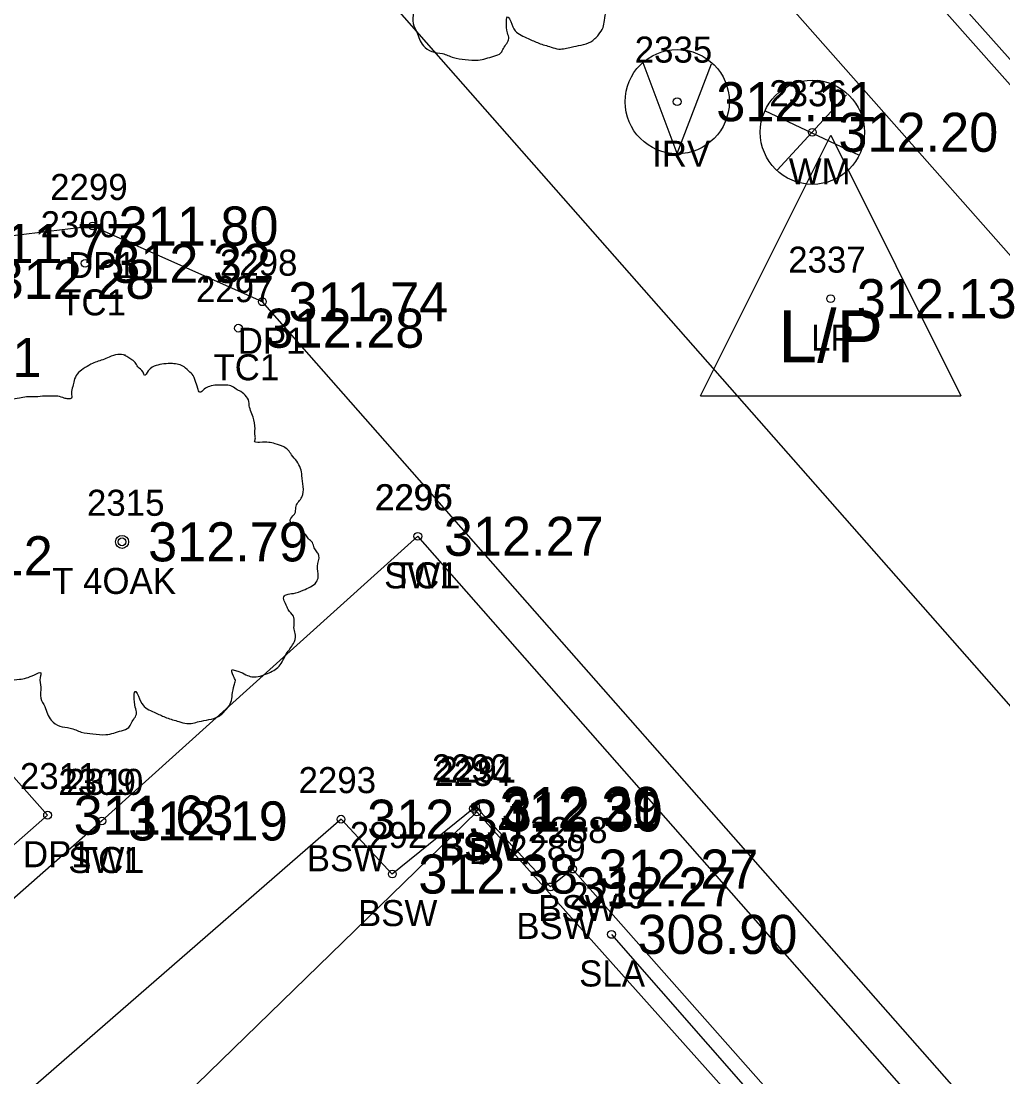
# Model space of a CAD drawing. Extents: x 1970076 to 1971136, y 803126 to 804215.
# Drawn here: x 1970346.97 to 1970384.66, y 803730.64 to 803771.17 of the extents above; entities that cross this region are included whole.
import ezdxf

# ---------------------------------------------------------------- set-up
doc = ezdxf.new("R2010")
doc.units = 0
for name, color, linetype in [('RD_EX_Bldg', 7, 'Continuous'), ('RD_EX_Bldg_txCode', 7, 'Continuous'), ('RD_EX_BldgApp', 7, 'Continuous'), ('RD_EX_Conc', 7, 'Continuous'), ('RD_EX_Conc_txCode', 7, 'Continuous'), ('RD_EX_Driveway', 7, 'Continuous'), ('RD_EX_Driveway_txCode', 7, 'Continuous'), ('RD_EX_Misc_txCode', 7, 'Continuous'), ('RD_EX_TX_Bldg_ELEV', 7, 'Continuous'), ('RD_EX_TX_Conc_ELEV', 7, 'Continuous'), ('RD_EX_TX_Driveway_ELEV', 7, 'Continuous'), ('RD_EX_TX_Misc_ELEV', 7, 'Continuous'), ('RD_EX_TX_UT_ELEV', 7, 'Continuous'), ('RD_EX_TX_VEG_ELEV', 7, 'Continuous'), ('RD_EX_UT', 7, 'Continuous'), ('RD_EX_UT_txCode', 7, 'Continuous'), ('RD_EX_VEG', 7, 'Continuous'), ('RD_EX_VEG_txCode', 7, 'Continuous'), ('RD_SMD_Locator', 7, 'Continuous')]:
    doc.layers.add(name, color=color, linetype=linetype)

msp = doc.modelspace()

# ---------------------------------------------------------------- linework, layer by layer
at = {"layer": 'RD_EX_Bldg'}
msp.add_lwpolyline([(1970316.239, 803648.649), (1970363.887, 803689.383), (1970360.372, 803693.374), (1970387.334, 803715.199), (1970364.462, 803740.807), (1970337.816, 803714.899), (1970333.809, 803719.759), (1970289.788, 803679.246), (1970316.239, 803648.649)], dxfattribs=at)
at = {"layer": 'RD_EX_BldgApp'}
for q in [(1970370.85, 803769.569), (1970373.476, 803769.532)]:
    msp.add_line((1970372.154, 803766.087), q, dxfattribs=at)
for radius in [2, 0.15]:
    msp.add_circle((1970372.154, 803768.079), radius, dxfattribs=at)
at = {"layer": 'RD_EX_Conc'}
msp.add_line((1970389.201, 803764.895), (1970371.192, 803785.158), dxfattribs=at)
for points in [[(1970403.64, 803748.467), (1970397.536, 803754.406), (1970390.789, 803761.917), (1970388.776, 803764.406), (1970370.879, 803784.584), (1970367.637, 803785.738), (1970364.866, 803784.899)], [(1970403.64, 803748.467), (1970400.496, 803744.573), (1970364.866, 803784.899)], [(1970388.043, 803714.574), (1970387.812, 803720.9), (1970384.41, 803726.133), (1970362.198, 803751.392), (1970350.072, 803740.463), (1970336.455, 803728.473)], [(1970388.043, 803714.574), (1970384.866, 803718.144), (1970385.631, 803718.829), (1970368.137, 803738.615), (1970367.294, 803737.93), (1970364.409, 803741.02), (1970364.338, 803740.936), (1970361.218, 803738.424), (1970359.252, 803740.53), (1970341.72, 803725.277)]]:
    msp.add_lwpolyline(points, dxfattribs=at)
at = {"layer": 'RD_EX_Driveway'}
for points in [[(1970401.094, 803743.669), (1970397.555, 803740.019), (1970391.952, 803738.507), (1970389.106, 803740.151), (1970358.957, 803774.425), (1970357.83, 803778.256), (1970359.349, 803782.137), (1970363.728, 803785.997), (1970367.42, 803786.267), (1970367.42, 803786.267), (1970371.192, 803785.158)], [(1970361.584, 803685.25), (1970385.155, 803706.07), (1970389.475, 803713.845), (1970389.303, 803721.405), (1970385.523, 803727.117), (1970356.232, 803760.398), (1970349.717, 803763.304), (1970344.215, 803762.632), (1970339.473, 803759.052), (1970338.114, 803753.777), (1970339.901, 803749.792), (1970347.988, 803740.685), (1970335.512, 803729.688)]]:
    msp.add_lwpolyline(points, dxfattribs=at)
at = {"layer": 'RD_EX_UT'}
for p, q in [((1970375.989, 803765.446), (1970378.657, 803768.342)), ((1970375.508, 803767.741), (1970379.139, 803766.028)), ((1970373.046, 803756.791), (1970378.046, 803766.791)), ((1970378.046, 803766.791), (1970383.046, 803756.791)), ((1970373.046, 803756.791), (1970383.046, 803756.791))]:
    msp.add_line(p, q, dxfattribs=at)
msp.add_circle((1970377.342, 803766.904), 2, dxfattribs=at)
at = {"layer": 'RD_EX_VEG'}
msp.add_line((1970369.634, 803736.106), (1970383.155, 803720.666), dxfattribs=at)
for centre, radius in [((1970350.846, 803751.179), 0.25), ((1970350.834, 803751.16), 0.0001)]:
    msp.add_circle(centre, radius, dxfattribs=at)
for points in [[(1970365.264, 803784.246), (1970364.964, 803784.271), (1970364.639, 803784.171), (1970364.39, 803784.071), (1970364.165, 803783.996), (1970363.94, 803783.896), (1970363.64, 803783.721), (1970363.415, 803783.521), (1970363.29, 803783.272), (1970363.24, 803783.047), (1970363.19, 803782.772), (1970363.19, 803782.597), (1970363.065, 803782.572), (1970362.915, 803782.597), (1970362.665, 803782.672), (1970362.415, 803782.672), (1970362.165, 803782.672), (1970361.816, 803782.647), (1970361.466, 803782.647), (1970361.191, 803782.597), (1970360.866, 803782.547), (1970360.491, 803782.422), (1970360.141, 803782.297), (1970359.842, 803782.047), (1970359.592, 803781.572), (1970359.467, 803781.222), (1970359.317, 803780.973), (1970359.467, 803780.523), (1970359.642, 803780.173), (1970359.667, 803779.973), (1970359.742, 803779.548), (1970359.842, 803779.323), (1970359.966, 803779.123), (1970359.892, 803779.098), (1970359.517, 803779.048), (1970359.217, 803778.948), (1970358.792, 803778.724), (1970358.567, 803778.499), (1970358.467, 803778.174), (1970358.442, 803777.824), (1970358.342, 803777.624), (1970358.267, 803777.349), (1970358.242, 803777.274), (1970358.192, 803776.949), (1970358.292, 803776.499), (1970358.317, 803776.15), (1970358.442, 803775.925), (1970358.592, 803775.75), (1970358.767, 803775.5), (1970359.167, 803775.275), (1970359.492, 803775.175), (1970359.692, 803775.15), (1970359.517, 803774.65), (1970359.467, 803774.3), (1970359.342, 803773.901), (1970359.342, 803773.826), (1970359.292, 803773.351), (1970359.442, 803773.026), (1970359.517, 803772.651), (1970359.692, 803772.426), (1970359.966, 803772.126), (1970360.291, 803771.902), (1970360.791, 803771.777), (1970361.191, 803771.802), (1970361.766, 803771.976), (1970362.016, 803772.051), (1970361.991, 803771.877), (1970362.016, 803771.502), (1970362.016, 803771.077), (1970362.165, 803770.752), (1970362.265, 803770.477), (1970362.415, 803770.227), (1970362.74, 803770.002), (1970363.14, 803769.927), (1970363.565, 803769.777), (1970364.015, 803769.702), (1970364.514, 803769.677), (1970365.114, 803769.827), (1970365.389, 803769.952), (1970365.489, 803770.127), (1970365.689, 803770.502), (1970365.639, 803770.727), (1970365.664, 803771.327), (1970365.764, 803771.152), (1970365.939, 803770.802), (1970366.439, 803770.502), (1970366.838, 803770.327), (1970367.313, 803770.177), (1970367.613, 803770.102), (1970368.088, 803770.177), (1970368.463, 803770.252), (1970368.838, 803770.377), (1970369.137, 803770.652), (1970369.312, 803770.927), (1970369.362, 803771.202), (1970369.437, 803771.577), (1970369.487, 803771.752)], [(1970350.978, 803758.346), (1970350.678, 803758.371), (1970350.353, 803758.271), (1970350.103, 803758.171), (1970349.879, 803758.096), (1970349.654, 803757.996), (1970349.354, 803757.821), (1970349.129, 803757.621), (1970349.004, 803757.371), (1970348.954, 803757.146), (1970348.904, 803756.872), (1970348.904, 803756.697), (1970348.779, 803756.672), (1970348.629, 803756.697), (1970348.379, 803756.772), (1970348.129, 803756.772), (1970347.879, 803756.772), (1970347.53, 803756.747), (1970347.18, 803756.747), (1970346.905, 803756.697), (1970346.58, 803756.647), (1970346.205, 803756.522), (1970345.855, 803756.397), (1970345.555, 803756.147), (1970345.306, 803755.672), (1970345.181, 803755.322), (1970345.031, 803755.072), (1970345.181, 803754.623), (1970345.356, 803754.273), (1970345.38, 803754.073), (1970345.455, 803753.648), (1970345.555, 803753.423), (1970345.68, 803753.223), (1970345.605, 803753.198), (1970345.231, 803753.148), (1970344.931, 803753.048), (1970344.506, 803752.823), (1970344.281, 803752.598), (1970344.181, 803752.274), (1970344.156, 803751.924), (1970344.056, 803751.724), (1970343.981, 803751.449), (1970343.956, 803751.374), (1970343.906, 803751.049), (1970344.006, 803750.599), (1970344.031, 803750.249), (1970344.156, 803750.025), (1970344.306, 803749.85), (1970344.481, 803749.6), (1970344.881, 803749.375), (1970345.206, 803749.275), (1970345.405, 803749.25), (1970345.231, 803748.75), (1970345.181, 803748.4), (1970345.056, 803748), (1970345.056, 803747.926), (1970345.006, 803747.451), (1970345.156, 803747.126), (1970345.231, 803746.751), (1970345.405, 803746.526), (1970345.68, 803746.226), (1970346.005, 803746.001), (1970346.505, 803745.876), (1970346.905, 803745.901), (1970347.48, 803746.076), (1970347.729, 803746.151), (1970347.704, 803745.976), (1970347.729, 803745.601), (1970347.729, 803745.177), (1970347.879, 803744.852), (1970347.979, 803744.577), (1970348.129, 803744.327), (1970348.454, 803744.102), (1970348.854, 803744.027), (1970349.279, 803743.877), (1970349.729, 803743.802), (1970350.228, 803743.777), (1970350.828, 803743.927), (1970351.103, 803744.052), (1970351.203, 803744.227), (1970351.403, 803744.602), (1970351.353, 803744.827), (1970351.378, 803745.427), (1970351.478, 803745.252), (1970351.653, 803744.902), (1970352.153, 803744.602), (1970352.552, 803744.427), (1970353.027, 803744.277), (1970353.327, 803744.202), (1970353.802, 803744.277), (1970354.177, 803744.352), (1970354.551, 803744.477), (1970354.851, 803744.752), (1970355.026, 803745.027), (1970355.076, 803745.302), (1970355.151, 803745.676), (1970355.201, 803745.851)], [(1970355.201, 803745.851), (1970355.126, 803746.026), (1970355.076, 803746.276), (1970355.151, 803746.251), (1970355.326, 803746.201), (1970355.601, 803746.076), (1970355.826, 803746.001), (1970356.151, 803746.026), (1970356.426, 803746.126), (1970356.875, 803746.401), (1970357.15, 803746.876), (1970357.425, 803747.276), (1970357.5, 803747.601), (1970357.45, 803747.826), (1970357.425, 803748.325), (1970357.225, 803748.575), (1970357.175, 803748.7), (1970357.075, 803749.1), (1970357.15, 803749.15), (1970357.425, 803749.2), (1970357.8, 803749.325), (1970358.075, 803749.45), (1970358.3, 803749.625), (1970358.375, 803749.85), (1970358.35, 803750.249), (1970358.4, 803750.649), (1970358.325, 803750.799), (1970358.225, 803750.949), (1970358.15, 803751.149), (1970358, 803751.299), (1970357.9, 803751.449), (1970357.8, 803751.549), (1970357.675, 803751.699), (1970357.5, 803751.824), (1970357.35, 803751.874), (1970357.3, 803752.024), (1970357.45, 803752.224), (1970357.5, 803752.324), (1970357.525, 803752.548), (1970357.75, 803752.898), (1970357.8, 803753.298), (1970357.75, 803753.723), (1970357.7, 803753.998), (1970357.55, 803754.273), (1970357.35, 803754.523), (1970357.225, 803754.698), (1970357.05, 803754.822), (1970356.726, 803754.947), (1970356.476, 803754.997), (1970356.126, 803754.997), (1970355.926, 803755.047), (1970355.951, 803755.097), (1970355.951, 803755.247), (1970355.951, 803755.522), (1970355.876, 803755.972), (1970355.726, 803756.472), (1970355.726, 803756.497), (1970355.626, 803756.747), (1970355.401, 803756.947), (1970355.226, 803757.046), (1970355.026, 803757.171), (1970354.776, 803757.196), (1970354.477, 803757.196), (1970354.202, 803757.146), (1970354.002, 803757.046), (1970353.827, 803756.922), (1970353.752, 803757.071), (1970353.652, 803757.371), (1970353.602, 803757.521), (1970353.452, 803757.696), (1970353.227, 803757.896), (1970352.777, 803758.021), (1970352.153, 803757.946), (1970351.853, 803757.746), (1970351.703, 803757.571), (1970351.653, 803757.696), (1970351.453, 803757.896), (1970351.353, 803758.071), (1970351.178, 803758.196), (1970351.028, 803758.296), (1970350.928, 803758.346)]]:
    msp.add_spline(points, degree=3, dxfattribs=at)
at = {"layer": 'RD_SMD_Locator'}
for centre in [(1970377.342, 803766.904), (1970349.717, 803763.304), (1970349.43, 803761.874), (1970356.232, 803760.398), (1970378.046, 803760.515), (1970355.314, 803759.382), (1970362.198, 803751.392), (1970362.198, 803751.392), (1970350.846, 803751.179), (1970364.338, 803740.936), (1970364.409, 803741.02), (1970364.462, 803740.807), (1970347.988, 803740.685), (1970350.072, 803740.463), (1970350.072, 803740.463), (1970359.252, 803740.53), (1970361.218, 803738.424), (1970368.137, 803738.615), (1970367.294, 803737.93), (1970369.634, 803736.106)]:
    msp.add_circle(centre, 0.15, dxfattribs=at)

# ---------------------------------------------------------------- texts
at = {"layer": 'RD_EX_Bldg_txCode'}
for s, p in [('2234', (1970362.832, 803741.807)), ('B', (1970364.155, 803738.807))]:
    msp.add_text(s, height=1, dxfattribs=at).set_placement(p)
at = {"layer": 'RD_EX_Conc_txCode'}
for s, p in [('2300', (1970347.721, 803762.874)), ('2297', (1970353.684, 803760.382)), ('TC1', (1970348.469, 803759.874)), ('TC1', (1970354.353, 803757.382)), ('2296', (1970360.544, 803752.392)), ('2295', (1970360.568, 803752.392)), ('SWL', (1970360.907, 803749.392)), ('TC1', (1970361.237, 803749.392)), ('2290', (1970362.74, 803742.02)), ('2291', (1970362.992, 803741.936)), ('2309', (1970348.403, 803741.463)), ('2310', (1970348.686, 803741.463)), ('2293', (1970357.622, 803741.53)), ('2288', (1970366.507, 803739.615)), ('2292', (1970359.588, 803739.424)), ('BSW', (1970363.023, 803738.936)), ('BSW', (1970363.094, 803739.02)), ('2289', (1970365.664, 803738.93)), ('SWL', (1970348.781, 803738.463)), ('TC1', (1970349.111, 803738.463)), ('BSW', (1970357.937, 803738.53)), ('BSW', (1970359.903, 803736.424)), ('BSW', (1970366.822, 803736.615)), ('BSW', (1970365.979, 803735.93))]:
    msp.add_text(s, height=1, dxfattribs=at).set_placement(p)
at = {"layer": 'RD_EX_Driveway_txCode'}
for s, p in [('2299', (1970348.087, 803764.304)), ('DP1', (1970348.772, 803761.304)), ('2298', (1970354.602, 803761.398)), ('DP1', (1970355.287, 803758.398)), ('2311', (1970346.925, 803741.685)), ('DP1', (1970347.043, 803738.685))]:
    msp.add_text(s, height=1, dxfattribs=at).set_placement(p)
at = {"layer": 'RD_EX_Misc_txCode'}
for s, p in [('2335', (1970370.524, 803769.579)), ('IRV', (1970371.193, 803765.579))]:
    msp.add_text(s, height=1, dxfattribs=at).set_placement(p)
at = {"layer": 'RD_EX_TX_Bldg_ELEV'}
msp.add_text('312.30', height=1.5, dxfattribs=at).set_placement((1970365.462, 803740.057))
at = {"layer": 'RD_EX_TX_Conc_ELEV'}
for s, p in [('312.32', (1970350.43, 803761.124)), ('312.28', (1970345.957, 803760.509)), ('312.28', (1970356.314, 803758.632)), ('312.21', (1970341.617, 803757.505)), ('312.27', (1970363.198, 803750.642)), ('312.27', (1970363.198, 803750.642)), ('312.12', (1970342.052, 803749.895)), ('312.29', (1970365.409, 803740.27)), ('312.31', (1970365.338, 803740.186)), ('312.19', (1970351.072, 803739.713)), ('312.19', (1970351.072, 803739.713)), ('312.34', (1970360.252, 803739.78)), ('312.27', (1970369.137, 803737.865)), ('312.38', (1970362.218, 803737.674)), ('312.27', (1970368.294, 803737.18))]:
    msp.add_text(s, height=1.5, dxfattribs=at).set_placement(p)
at = {"layer": 'RD_EX_TX_Driveway_ELEV'}
for s, p in [('311.80', (1970350.717, 803762.554)), ('311.77', (1970345.215, 803761.882)), ('311.74', (1970357.232, 803759.648)), ('311.63', (1970348.988, 803739.935))]:
    msp.add_text(s, height=1.5, dxfattribs=at).set_placement(p)
at = {"layer": 'RD_EX_TX_Misc_ELEV'}
msp.add_text('312.11', height=1.5, dxfattribs=at).set_placement((1970373.654, 803767.329))
at = {"layer": 'RD_EX_TX_UT_ELEV'}
for s, p in [('312.20', (1970378.342, 803766.154)), ('312.13', (1970379.046, 803759.765))]:
    msp.add_text(s, height=1.5, dxfattribs=at).set_placement(p)
at = {"layer": 'RD_EX_TX_VEG_ELEV'}
for s, p in [('312.79', (1970351.846, 803750.429)), ('308.90', (1970370.634, 803735.356))]:
    msp.add_text(s, height=1.5, dxfattribs=at).set_placement(p)
at = {"layer": 'RD_EX_UT'}
msp.add_text('L/P', height=2, dxfattribs=at).set_placement((1970376.038, 803758.073))
at = {"layer": 'RD_EX_UT_txCode'}
for s, p in [('2336', (1970375.688, 803767.904)), ('WM', (1970376.436, 803764.904)), ('2337', (1970376.416, 803761.515)), ('LP', (1970377.29, 803758.515))]:
    msp.add_text(s, height=1, dxfattribs=at).set_placement(p)
at = {"layer": 'RD_EX_VEG_txCode'}
for s, p in [('2315', (1970349.5, 803752.179)), ('T 4OAK', (1970348.161, 803749.179)), ('2239', (1970368.004, 803737.106)), ('SLA', (1970368.39, 803734.106))]:
    msp.add_text(s, height=1, dxfattribs=at).set_placement(p)

doc.saveas('drawing.dxf')
